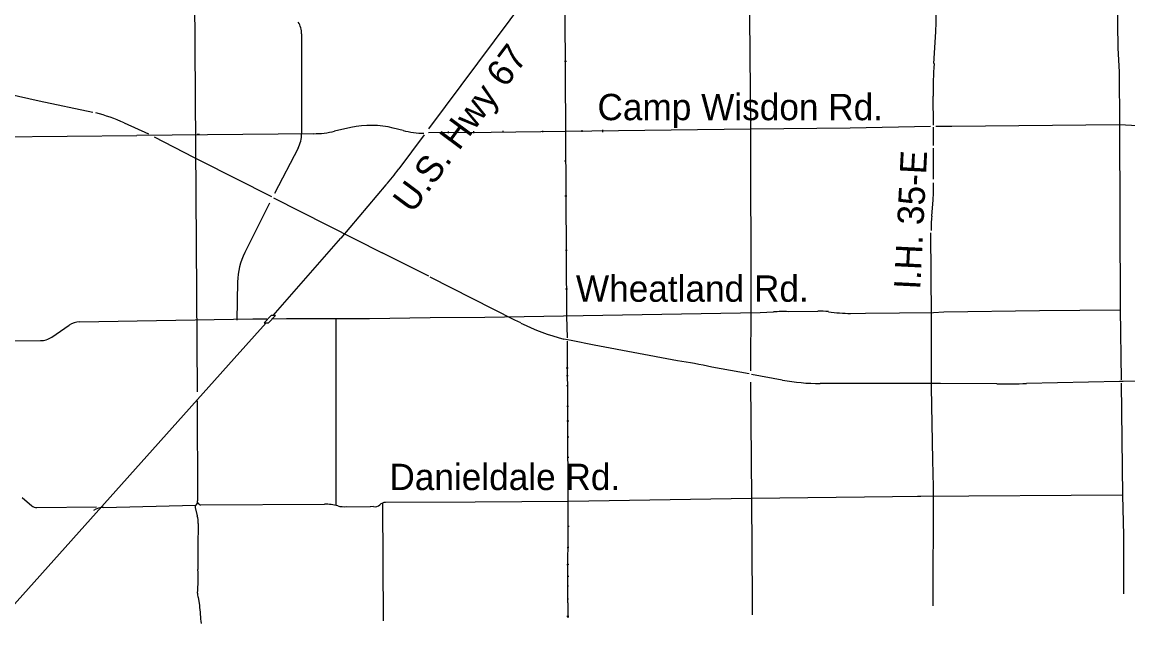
# Model space of a CAD drawing. Extents: x 105094 to 105814, y -291615 to -291123.
# Drawn here: x 105395.2 to 105446.1, y -291558.5 to -291530.7 of the extents above; entities that cross this region are included whole.
import ezdxf

# ---------------------------------------------------------------- set-up
doc = ezdxf.new("R2010")
doc.units = 0
doc.layers.add('G_MAP', color=7, linetype='Continuous')

msp = doc.modelspace()

# ---------------------------------------------------------------- linework, layer by layer
at = {"layer": 'G_MAP'}
for p, q in [((105403.058, -291518.577), (105403.252, -291547.706)), ((105423.73, -291522.407), (105413.909, -291535.612)), ((105408.06, -291531.24), (105408.06, -291535.829)), ((105437.165, -291532.606), (105437.246, -291531.143)), ((105420.155, -291532.489), (105420.248, -291532.489)), ((105391.025, -291533.239), (105395.988, -291534.311)), ((105395.988, -291534.311), (105398.456, -291534.837)), ((105437.146, -291535.432), (105437.13, -291534.098)), ((105399.901, -291535.331), (105401.023, -291535.838)), ((105410.329, -291535.551), (105409.582, -291535.719)), ((105412.73, -291535.681), (105412.28, -291535.57)), ((105437.149, -291536.368), (105437.146, -291535.535)), ((105387.476, -291536.038), (105400.477, -291535.916)), ((105408.614, -291535.83), (105400.477, -291535.916)), ((105401.272, -291535.974), (105403.093, -291536.91)), ((105403.361, -291535.871), (105403.255, -291535.871)), ((105413.705, -291535.884), (105412.53, -291537.453)), ((105414.813, -291535.722), (105414.813, -291535.806)), ((105415.985, -291535.8), (105415.985, -291535.709)), ((105417.342, -291535.777), (105417.342, -291535.703)), ((105419.154, -291535.696), (105419.154, -291535.761)), ((105420.978, -291535.748), (105420.978, -291535.67)), ((105421.909, -291535.654), (105421.909, -291535.754)), ((105407.898, -291536.493), (105406.82, -291538.574)), ((105437.143, -291537.915), (105437.149, -291536.494)), ((105403.093, -291536.91), (105403.368, -291537.046)), ((105403.368, -291537.046), (105406.681, -291538.725)), ((105420.168, -291537.082), (105420.242, -291537.082)), ((105437.143, -291538.467), (105437.143, -291538.083)), ((105411.936, -291538.186), (105409.869, -291540.628)), ((105406.581, -291539.029), (105405.446, -291541.299)), ((105406.765, -291538.774), (105411.764, -291541.306)), ((105420.261, -291538.696), (105420.177, -291538.7)), ((105437.058, -291539.627), (105437.125, -291538.869)), ((105406.756, -291544.19), (105409.869, -291540.628)), ((105437.049, -291544.219), (105437.026, -291540.395)), ((105420.281, -291541.202), (105420.2, -291541.199)), ((105413.912, -291542.384), (105411.764, -291541.306)), ((105405.116, -291542.648), (105405.086, -291544.403)), ((105417.878, -291544.4), (105413.98, -291542.436)), ((105420.2, -291542.969), (105420.297, -291542.969)), ((105416.499, -291544.27), (105429.166, -291544.061)), ((105429.166, -291544.061), (105429.782, -291544.028)), ((105430.461, -291544.015), (105431.817, -291543.993)), ((105437.043, -291547.487), (105437.049, -291544.219)), ((105396.565, -291545.184), (105397.363, -291544.639)), ((105397.844, -291544.486), (105405.813, -291544.351)), ((105404.954, -291546.176), (105406.433, -291544.529)), ((105405.816, -291544.351), (105406.465, -291544.345)), ((105406.672, -291544.351), (105407.369, -291544.328)), ((105407.369, -291544.328), (105411.183, -291544.332)), ((105418.151, -291544.537), (105417.878, -291544.4)), ((105420.462, -291545.346), (105420.129, -291545.278)), ((105390.6, -291545.382), (105396.039, -291545.348)), ((105404.954, -291546.176), (105393.9, -291558.515)), ((105420.236, -291546.596), (105420.329, -291546.596)), ((105428.652, -291546.883), (105426.937, -291546.567)), ((105420.329, -291546.973), (105420.249, -291546.973)), ((105428.72, -291547.258), (105428.772, -291552.612)), ((105430.185, -291547.163), (105428.768, -291546.906)), ((105433.903, -291547.316), (105431.928, -291547.319)), ((105437.462, -291547.322), (105433.903, -291547.316)), ((105440.059, -291547.329), (105437.462, -291547.322)), ((105445.695, -291547.232), (105441.428, -291547.322)), ((105445.869, -291547.232), (105445.695, -291547.232)), ((105447.708, -291547.19), (105445.869, -291547.232)), ((105420.249, -291547.416), (105420.336, -291547.422)), ((105403.258, -291548.11), (105403.278, -291552.724)), ((105420.339, -291548.372), (105420.262, -291548.375)), ((105420.262, -291549.04), (105420.355, -291549.043)), ((105420.355, -291549.783), (105420.281, -291549.783)), ((105420.278, -291550.707), (105420.362, -291550.707)), ((105395.2, -291552.568), (105395.649, -291552.942)), ((105398.947, -291553.018), (105403.184, -291552.919)), ((105403.428, -291552.899), (105409.114, -291552.873)), ((105411.784, -291552.825), (105411.819, -291558.233)), ((105445.847, -291552.46), (105436.404, -291552.52)), ((105437.12, -291557.295), (105437.136, -291552.58)), ((105395.876, -291553.023), (105398.63, -291553)), ((105403.161, -291553.024), (105403.252, -291553.406)), ((105410.137, -291552.977), (105411.222, -291552.996)), ((105411.364, -291552.983), (105411.222, -291552.996)), ((105420.304, -291553.881), (105420.375, -291553.878)), ((105420.362, -291554.869), (105420.284, -291554.876)), ((105420.362, -291555.648), (105420.275, -291555.654)), ((105420.362, -291556.2), (105420.281, -291556.203)), ((105420.349, -291556.649), (105420.278, -291556.655)), ((105403.297, -291557.159), (105403.362, -291557.521)), ((105420.352, -291557.243), (105420.281, -291557.253)), ((105437.125, -291557.552), (105437.12, -291557.295)), ((105437.125, -291557.552), (105437.12, -291557.295)), ((105420.271, -291558.018), (105420.359, -291558.018)), ((105420.271, -291558.018), (105420.359, -291558.018))]:
    msp.add_line(p, q, dxfattribs=at)
for points in [[(105428.587, -291520.04), (105428.713, -291535.628), (105428.736, -291543.637), (105428.72, -291546.744)], [(105420.297, -291545.217), (105420.265, -291544.225), (105420.181, -291527.435)], [(105445.711, -291535.419), (105445.701, -291532.993), (105445.646, -291531.886), (105445.61, -291529.719), (105445.601, -291528.165)], [(105413.899, -291535.767), (105416.783, -291535.754), (105420.203, -291535.716), (105428.72, -291535.609), (105433.303, -291535.561), (105437, -291535.477)], [(105437.246, -291535.477), (105437.992, -291535.477), (105445.701, -291535.409), (105454.809, -291535.915)], [(105445.795, -291547.151), (105445.746, -291543.906), (105445.714, -291535.406)], [(105411.183, -291544.332), (105413.983, -291544.287), (105416.499, -291544.27)], [(105433.329, -291544.093), (105434.016, -291544.086), (105437.143, -291544.061)], [(105437.143, -291544.061), (105437.614, -291544.025), (105442.016, -291543.964), (105445.737, -291543.928)], [(105409.633, -291544.335), (105409.63, -291546.948), (105409.63, -291552.906)], [(105420.313, -291557.411), (105420.326, -291552.748), (105420.297, -291545.372)], [(105425.358, -291546.273), (105421.528, -291545.552), (105420.462, -291545.346)], [(105445.898, -291557), (105445.895, -291554.304), (105445.853, -291552.47), (105445.795, -291547.303)], [(105437.136, -291552.58), (105437.136, -291552.073), (105437.107, -291550.842), (105437.043, -291547.487)], [(105436.555, -291552.522), (105428.765, -291552.606), (105420.342, -291552.754), (105416.05, -291552.783), (105411.928, -291552.79)], [(105428.772, -291552.612), (105428.794, -291557.35), (105428.795, -291557.966)], [(105403.3, -291553.765), (105403.284, -291554.834), (105403.294, -291555.877)], [(105420.313, -291557.411), (105420.32, -291558.099)], [(105420.313, -291557.411), (105420.32, -291558.099)]]:
    msp.add_lwpolyline(points, dxfattribs=at)
msp.add_lwpolyline([(105406.657, -291544.193), (105406.334, -291544.532), (105406.531, -291544.525), (105406.854, -291544.186)], close=True, dxfattribs=at)
for centre, radius, start, end in [((105426.875, -291530.398), 10.397, 355.8901, 2.1583), ((105406.993, -291531.24), 1.067, 0.0005, 30.6264), ((105453.591, -291533.743), 16.465, 176.039, 181.2342), ((105396.56, -291542.727), 8.115, 65.6919, 75.5301), ((105411.263, -291539.701), 4.254, 76.1726, 102.6834), ((105406.618, -291535.829), 1.442, 332.6076, 0), ((105408.579, -291531.257), 4.573, 270.4429, 282.6734), ((105413.826, -291531.248), 4.566, 256.1185, 268.3273), ((105406.487, -291533.162), 7.411, 317.3216, 324.6223), ((105432.594, -291538.467), 4.549, 354.9349, 0.0022), ((105445.34, -291540.355), 8.313, 174.978, 179.5436), ((105408.242, -291542.697), 3.126, 153.4345, 179.0917), ((105430.242, -291550.382), 6.37, 88.0377, 94.1419), ((105431.88, -291548.07), 4.078, 83.8904, 90.8881), ((105433.266, -291538.253), 5.841, 260.6229, 270.6188), ((105397.859, -291545.365), 0.88, 90.9657, 124.3404), ((105422.545, -291535.818), 9.764, 243.2599, 255.6767), ((105396.033, -291544.407), 0.942, 270.3522, 304.3363), ((105421.584, -291570.941), 24.955, 77.6141, 81.3029), ((105431.913, -291537.66), 9.659, 259.6968, 270.0892), ((105440.63, -291523.117), 24.218, 268.6494, 271.8895), ((105403.26, -291553.001), 0.102, 122.4769, 193.3159), ((105403.044, -291552.744), 0.235, 313.4814, 4.8178), ((105403.428, -291552.735), 0.165, 209.3194, 270.2265), ((105409.128, -291555.184), 2.311, 74.9805, 90.3608), ((105411.443, -291552.696), 0.298, 254.6104, 315.7326), ((105411.928, -291553.168), 0.378, 89.992, 135.7619), ((105395.873, -291552.672), 0.35, 230.2432, 270.4589), ((105398.968, -291553.913), 0.895, 91.3618, 122.4386), ((105402.558, -291553.683), 0.747, 353.6764, 21.7164), ((105409.992, -291551.964), 1.023, 254.9709, 278.1191), ((105397.512, -291556.278), 5.795, 353.2372, 3.9675), ((105403.648, -291557.005), 0.383, 173.2916, 203.7005), ((105428.243, -291555.733), 24.945, 184.1098, 186.0572)]:
    msp.add_arc(centre, radius, start, end, dxfattribs=at)

# ---------------------------------------------------------------- texts
for s, height, rotation, p in [('U.S. Hwy 67', 1.21107, 53.4205, (105413.154, -291539.541)), ('I.H. 35-E', 1.2111, 87.1247, (105436.531, -291543.016))]:
    msp.add_text(s, height=height, rotation=rotation, dxfattribs=at).set_placement(p)
for s, p in [('Camp Wisdon Rd.', (105421.679, -291535.208)), ('Wheatland Rd.', (105420.687, -291543.56)), ('Danieldale Rd.', (105412.102, -291552.222))]:
    msp.add_text(s, height=1.21107, dxfattribs=at).set_placement(p)

doc.saveas('drawing.dxf')
